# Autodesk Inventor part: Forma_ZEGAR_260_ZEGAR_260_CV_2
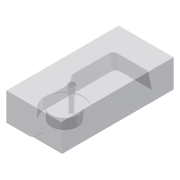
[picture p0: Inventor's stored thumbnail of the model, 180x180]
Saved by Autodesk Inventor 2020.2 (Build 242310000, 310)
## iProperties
Created: 2015-01
Part Number: Forma_ZEGAR_260_ZEGAR_260_CV_2
Material: Ogólny
Document SubType Name: Modeling
Designer: F.Stasiak
Density: 1 g/cm^3
Appearance: Domyślna
Catalog Web Link: www.expertbooks.pl
Manager: www.cadconsulting.pl
Company: Fabian Stasiak CAD Consulting
Author: F.Stasiak
Subject: Zbiór ćwiczeń. Autodesk Inventor 2020. Kurs Professional
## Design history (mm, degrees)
node "Forma_ZEGAR_260_ZEGAR_260_CV_Base"
feature "Rzeźbienie3"
feature "Bryła5::Forma_ZEGAR_260_ZEGAR_260_CV_Base"
tag "Bryła wyprowadzona1"
node "Bryła1"
feature "Forma_ZEGAR_260_ZEGAR_260_CV_Base_Bodies"
feature "Powierzchnia3"
body "Srf3"
